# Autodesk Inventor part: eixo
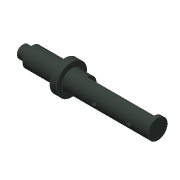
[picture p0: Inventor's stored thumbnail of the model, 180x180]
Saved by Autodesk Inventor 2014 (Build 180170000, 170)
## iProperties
Created: 2012-09
Part Number: eixo
Material: Generic
Document SubType Name: Modeling
Designer: TR-06
Density: 1 g/cm^3
Appearance: Default
Author: TR-06
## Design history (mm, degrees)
sketch "Sketch1"
  geometry: L1 (0, 0)-(0, 17.75); L2 (0, 17.75)-(28.9, 17.75); L3 (28.9, 17.75)-(28.9, 28); L4 (0, 0)-(389.8, 0); L5 (389.8, 0)-(389.8, 28); L6 (28.9, 28)-(117.7, 28); L7 (142.7, 43.6)-(117.7, 43.6); L8 (117.7, 43.6)-(117.7, 28); L9 (142.7, 28)-(142.7, 43.6); L10 (142.7, 28)-(389.8, 28)
  constraints: 20 end point, 6 perpendicular, 1 parallel, 1 vertical
  dimensions: "d0" = 17.75 distance of L1.start L1.end; "d1" = 28.9 distance of L1.end L2.end; "d4" = 389.8 distance of L1.start L4.end; "d5" = 28 distance of L4.end L5.end; "d9" = 25 distance of L7.start L7.end
revolve "Revolution1" sketch "Sketch1" stored, may be unused: angle "d10" = 90 deg
sketch "Sketch3"
  geometry: L1 (379.3, 0)-(185.5, 0); L2 (185.5, 0)-(185.5, 75.141); L3 (185.5, 75.141)-(379.3, 75.141); L4 (379.3, 75.141)-(379.3, 0); L5 (0, -17.75)-(0, 17.75) reference; 1 further point
  constraints: 8 end point, 2 parallel, 1 horizontal, 1 perpendicular
  dimensions: "d11" = 185.5 distance between parallel lines of L5 L2; "d12" = 193.8 distance between parallel lines of L2 L4
extrude "Extrusion1" cut sketch "Sketch3" stored distance "d13" = 87.85; taper "d14" = 0 deg
sketch "Sketch4"
  geometry: L1 (193.8, 56)-(193.8, 0) reference; L2 (0, 0)-(0, 56) reference; C1 r 6.25 at (46.9, 28); C2 r 6.25 at (146.9, 28); 1 further point
  constraints: 2 centre point
  dimensions: "d15" = 12.5 diameter of C1; "d16" = 12.5 diameter of C2; "d17" = 100 distance of C1.centre C2.centre; "d18" = 46.9 distance from line of L2 C1.centre; "d19" = 46.9 distance from line of L1 C2.centre
extrude "Extrusion2" cut sketch "Sketch4" stored distance "d20" = 87.85; taper "d21" = 0 deg
chamfer "Chamfer1" distance "d22" = 3; stored, may be unused: second distance "d23" = 2, angle "d24" = 45 deg
sketch "Esboço5"
  geometry: C1 r 43.6 at (0, 0) reference; C2 r 28 at (0, 0) reference
extrude "Extrusão3" cut sketch "Esboço5" distance "d25" = 5; taper "d26" = 0 deg
body "Solid1"
